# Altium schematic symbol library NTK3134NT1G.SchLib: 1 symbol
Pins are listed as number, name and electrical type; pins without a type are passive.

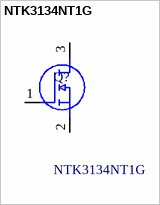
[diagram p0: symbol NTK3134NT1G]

## NTK3134NT1G
designator Q?
Power MOSFET; Manufacturer_Name: onsemi; Geometry.Height: 0.55mm
footprint NTK3134NT1G
pins: 1 G, 2 S, 3 D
